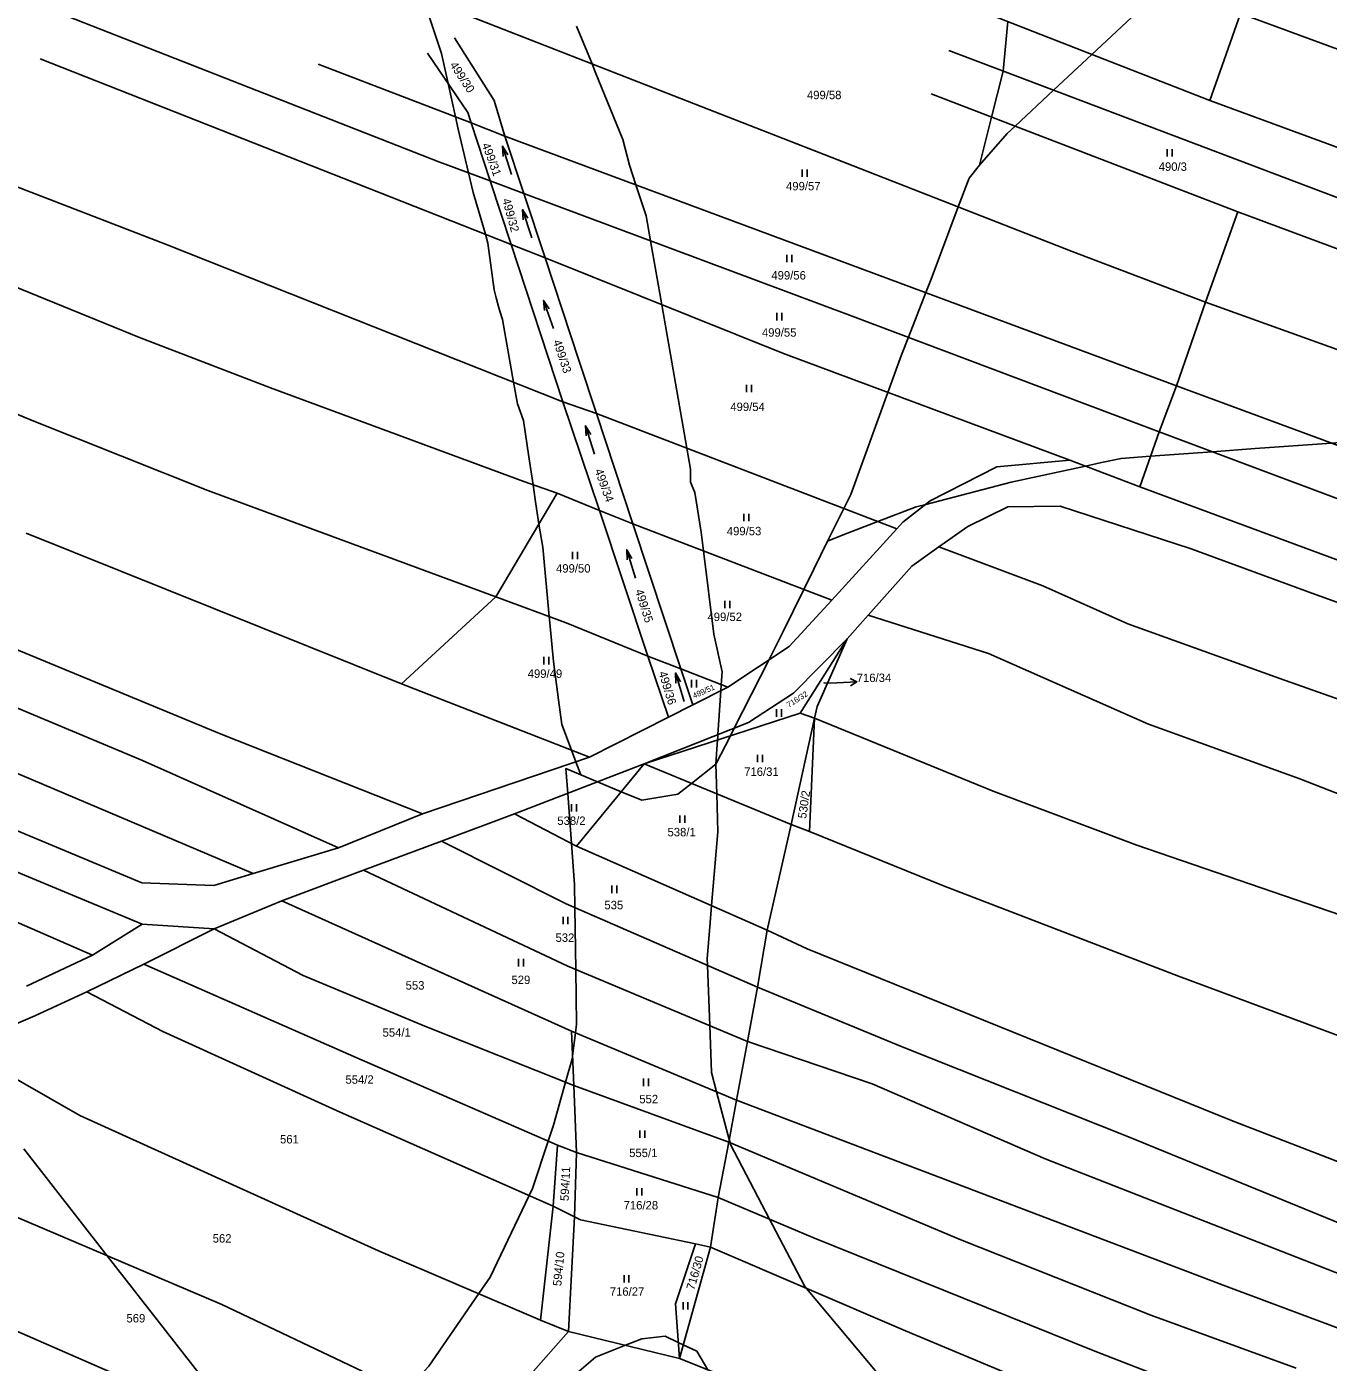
# Model space of a CAD drawing. Extents: x -749173 to -746119, y -1132678 to -1130338.
# Drawn here: x -748430.5 to -748168.2, y -1130971 to -1130701.9 of the extents above; entities that cross this region are included whole.
import ezdxf

# ---------------------------------------------------------------- set-up
doc = ezdxf.new("R2010")
doc.units = 0
for name, color, linetype in [('Vrstva 1', 7, 'Continuous'), ('Vrstva 16', 7, 'Continuous'), ('Vrstva 18', 7, 'Continuous'), ('Vrstva 25', 7, 'Continuous'), ('Vrstva 52', 7, 'Continuous'), ('Vrstva 6', 7, 'Continuous')]:
    doc.layers.add(name, color=color, linetype=linetype)

msp = doc.modelspace()

# ---------------------------------------------------------------- linework, layer by layer
at = {"layer": 'Vrstva 1'}
for points in [[(-748336.28, -1130716.76), (-748344.32, -1130704.11)], [(-748349.74, -1130707.22), (-748341.63, -1130719.17)], [(-748334.14, -1130723.95), (-748336.28, -1130716.76)], [(-748341.63, -1130719.17), (-748340.95, -1130721.23)], [(-748340.95, -1130721.23), (-748337.1, -1130732.95)], [(-748330.34, -1130735.47), (-748334.14, -1130723.95)], [(-748337.1, -1130732.95), (-748332.9, -1130745.74)], [(-748326.07, -1130748.44), (-748330.34, -1130735.47)], [(-748332.9, -1130745.74), (-748322.49, -1130777.44)], [(-748319.21, -1130769.27), (-748326.07, -1130748.44)], [(-748315.72, -1130779.81), (-748319.21, -1130769.27)], [(-748322.49, -1130777.44), (-748315.11, -1130799.35)], [(-748308.36, -1130802.04), (-748315.72, -1130779.81)], [(-748235.03, -1130790.57), (-748248.44, -1130797.43)], [(-748220.29, -1130789.23), (-748235.03, -1130790.57)], [(-748206.22, -1130794.61), (-748220.29, -1130789.23)], [(-748116.18, -1130827.89), (-748206.22, -1130794.61)], [(-748248.44, -1130797.43), (-748253.94, -1130801.72)], [(-748240.86, -1130802.57), (-748232.82, -1130798.59)], [(-748232.82, -1130798.59), (-748222.25, -1130798.5)], [(-748222.25, -1130798.5), (-748195.87, -1130807.09)], [(-748315.11, -1130799.35), (-748305.32, -1130828.72)], [(-748253.94, -1130801.72), (-748255.16, -1130803.06)], [(-748298.68, -1130831.28), (-748308.36, -1130802.04)], [(-748255.16, -1130803.06), (-748268.27, -1130817.4)], [(-748246.71, -1130806.7), (-748240.86, -1130802.57)], [(-748252.18, -1130810.57), (-748246.71, -1130806.7)], [(-748195.87, -1130807.09), (-748171.55, -1130816.01)], [(-748260.98, -1130820.46), (-748252.18, -1130810.57)], [(-748268.27, -1130817.4), (-748276.84, -1130826.78)], [(-748171.55, -1130816.01), (-748091.95, -1130844.69)], [(-748265.19, -1130825.19), (-748260.98, -1130820.46)], [(-748265.19, -1130825.19), (-748276.01, -1130836.18)], [(-748271.25, -1130838.88), (-748265.19, -1130825.19)], [(-748305.32, -1130828.72), (-748301.18, -1130841.02)], [(-748276.84, -1130826.78), (-748289.25, -1130834.98)], [(-748296.28, -1130838.54), (-748298.68, -1130831.28)], [(-748407.29, -1130874.39), (-748504.41, -1130833.78)], [(-748289.25, -1130834.98), (-748296.28, -1130838.54)], [(-748285.08, -1130842.06), (-748276.01, -1130836.18)], [(-748296.28, -1130838.54), (-748301.18, -1130841.02)], [(-748271.76, -1130841.22), (-748271.25, -1130838.88)], [(-748301.18, -1130841.02), (-748317.07, -1130849.07)], [(-748306.12, -1130850.42), (-748285.08, -1130842.06)], [(-748276.46, -1130862.6), (-748271.76, -1130841.22)], [(-748317.07, -1130849.07), (-748350.77, -1130860.5)], [(-748332.19, -1130860.47), (-748306.12, -1130850.42)], [(-748464.71, -1130858.77), (-748407.23, -1130882.69)], [(-748350.77, -1130860.5), (-748367.71, -1130867.32)], [(-748346.93, -1130865.99), (-748332.19, -1130860.47)], [(-748281.3, -1130883.89), (-748276.46, -1130862.6)], [(-748362.61, -1130871.86), (-748346.93, -1130865.99)], [(-748367.71, -1130867.32), (-748384.89, -1130872.51)], [(-748379.12, -1130878.04), (-748362.61, -1130871.86)], [(-748392.79, -1130874.89), (-748407.29, -1130874.39)], [(-748384.89, -1130872.51), (-748392.79, -1130874.89)], [(-748392.75, -1130883.62), (-748379.12, -1130878.04)], [(-748379.12, -1130878.04), (-748320.72, -1130904.27)], [(-748417.27, -1130888.93), (-748407.23, -1130882.69)], [(-748407.23, -1130882.69), (-748392.75, -1130883.62)], [(-748406.9, -1130890.75), (-748392.75, -1130883.62)], [(-748283.22, -1130895.4), (-748281.3, -1130883.89)], [(-748430.56, -1130895.23), (-748417.27, -1130888.93)], [(-748418.37, -1130896.38), (-748406.9, -1130890.75)], [(-748285.26, -1130906.35), (-748283.22, -1130895.4)], [(-748428.88, -1130901.17), (-748418.37, -1130896.38)], [(-748443.77, -1130907.57), (-748428.88, -1130901.17)], [(-748320.72, -1130904.27), (-748320.27, -1130915.24)], [(-748287.49, -1130918.18), (-748285.26, -1130906.35)], [(-748320.27, -1130915.24), (-748319.71, -1130928.71)], [(-748289.04, -1130926.63), (-748287.49, -1130918.18)], [(-748291.2, -1130937.79), (-748289.04, -1130926.63)], [(-748319.71, -1130928.71), (-748320.15, -1130941.67)], [(-748292.72, -1130947.82), (-748291.2, -1130937.79)], [(-748320.15, -1130941.67), (-748321.33, -1130964.79)], [(-748298.99, -1130970.22), (-748292.72, -1130947.82)], [(-748321.33, -1130964.79), (-748338.46, -1130984.21)], [(-748225.2, -1130999.57), (-748298.99, -1130970.22)]]:
    msp.add_lwpolyline(points, dxfattribs=at)
at = {"layer": 'Vrstva 16'}
msp.add_line((-748264.6, -1130833.18), (-748263.26, -1130833.87), dxfattribs=at)
for points in [[(-748269.9, -1130834.17), (-748267.26, -1130834.05)], [(-748267.26, -1130834.05), (-748263.26, -1130833.87), (-748264.53, -1130834.68)]]:
    msp.add_lwpolyline(points, dxfattribs=at)
at = {"layer": 'Vrstva 25'}
for p, q in [((-748332.82, -1130731.65), (-748334.64, -1130725.93)), ((-748200.71, -1130726.51), (-748200.71, -1130728.01)), ((-748199.71, -1130728.01), (-748199.71, -1130726.51)), ((-748274.26, -1130730.64), (-748274.26, -1130732.14)), ((-748273.26, -1130732.14), (-748273.26, -1130730.64)), ((-748328.69, -1130744.39), (-748330.61, -1130738.71)), ((-748277.32, -1130747.83), (-748277.32, -1130749.33)), ((-748276.32, -1130749.33), (-748276.32, -1130747.83)), ((-748324.36, -1130762.67), (-748326.36, -1130757.01)), ((-748279.33, -1130759.54), (-748279.33, -1130761.04)), ((-748278.33, -1130761.04), (-748278.33, -1130759.54)), ((-748285.45, -1130774.02), (-748285.45, -1130775.52)), ((-748284.45, -1130775.52), (-748284.45, -1130774.02)), ((-748316.09, -1130787.99), (-748317.93, -1130782.29)), ((-748286, -1130800), (-748286, -1130801.5)), ((-748285, -1130801.5), (-748285, -1130800)), ((-748307.84, -1130812.99), (-748309.6, -1130807.25)), ((-748320.55, -1130807.67), (-748320.55, -1130809.17)), ((-748319.55, -1130809.17), (-748319.55, -1130807.67)), ((-748289.8, -1130817.54), (-748289.8, -1130819.04)), ((-748288.8, -1130819.04), (-748288.8, -1130817.54)), ((-748326.33, -1130828.87), (-748326.33, -1130830.37)), ((-748325.33, -1130830.37), (-748325.33, -1130828.87)), ((-748298.04, -1130837.83), (-748299.8, -1130832.09)), ((-748296.53, -1130833.5), (-748296.53, -1130835)), ((-748295.53, -1130835), (-748295.53, -1130833.5)), ((-748279.42, -1130839.41), (-748279.42, -1130840.91)), ((-748278.42, -1130840.91), (-748278.42, -1130839.41)), ((-748283.27, -1130848.58), (-748283.27, -1130850.08)), ((-748282.27, -1130850.08), (-748282.27, -1130848.58)), ((-748320.75, -1130858.52), (-748320.75, -1130860.02)), ((-748319.75, -1130860.02), (-748319.75, -1130858.52)), ((-748298.91, -1130860.81), (-748298.91, -1130862.31)), ((-748297.91, -1130862.31), (-748297.91, -1130860.81)), ((-748312.61, -1130874.94), (-748312.61, -1130876.44)), ((-748311.61, -1130876.44), (-748311.61, -1130874.94)), ((-748322.44, -1130881.21), (-748322.44, -1130882.71)), ((-748321.44, -1130882.71), (-748321.44, -1130881.21)), ((-748331.4, -1130889.71), (-748331.4, -1130891.21)), ((-748330.4, -1130891.21), (-748330.4, -1130889.71)), ((-748306.24, -1130913.83), (-748306.24, -1130915.33)), ((-748305.24, -1130915.33), (-748305.24, -1130913.83)), ((-748306.95, -1130924.29), (-748306.95, -1130925.79)), ((-748305.95, -1130925.79), (-748305.95, -1130924.29)), ((-748307.56, -1130935.88), (-748307.56, -1130937.38)), ((-748306.56, -1130937.38), (-748306.56, -1130935.88)), ((-748310.15, -1130953.45), (-748310.15, -1130954.95)), ((-748309.15, -1130954.95), (-748309.15, -1130953.45)), ((-748298.26, -1130958.89), (-748298.26, -1130960.39)), ((-748297.26, -1130960.39), (-748297.26, -1130958.89))]:
    msp.add_line(p, q, dxfattribs=at)
for points in [[(-748334.51, -1130727.99), (-748334.64, -1130725.93), (-748333.56, -1130727.69)], [(-748330.44, -1130740.76), (-748330.61, -1130738.71), (-748329.5, -1130740.44)], [(-748326.16, -1130759.06), (-748326.36, -1130757.01), (-748325.22, -1130758.73)], [(-748317.79, -1130784.34), (-748317.93, -1130782.29), (-748316.84, -1130784.03)], [(-748309.49, -1130809.31), (-748309.6, -1130807.25), (-748308.54, -1130809.02)], [(-748299.69, -1130834.15), (-748299.8, -1130832.09), (-748298.74, -1130833.86)]]:
    msp.add_lwpolyline(points, dxfattribs=at)
at = {"layer": 'Vrstva 52'}
for points in [[(-748349.45, -1130699.63), (-748346.94, -1130707.25), (-748345.59, -1130713.34), (-748344.11, -1130720.02), (-748343.56, -1130722.5), (-748341.49, -1130731.31), (-748340.56, -1130735.25), (-748338.09, -1130743.69), (-748337.56, -1130745.5), (-748336.31, -1130754.87), (-748335.89, -1130756.5), (-748335.44, -1130758.25), (-748335.16, -1130759.16), (-748334.62, -1130760.87)], [(-748291.62, -1130850.5), (-748291.42, -1130847.43), (-748291.3, -1130845.61), (-748291.26, -1130845.05), (-748291.22, -1130844.5), (-748290.63, -1130835.68), (-748290.55, -1130834.47), (-748290.37, -1130831.87), (-748292.06, -1130824.25), (-748294.16, -1130807.48), (-748294.62, -1130803.75), (-748295.87, -1130795.75), (-748296.75, -1130793.62), (-748296.75, -1130791), (-748297.48, -1130786.81), (-748302.55, -1130757.88), (-748304.81, -1130745), (-748305.69, -1130740), (-748307.75, -1130733.75), (-748309.06, -1130729.75), (-748310.37, -1130724.62), (-748315.94, -1130710.96), (-748316.59, -1130709.36), (-748319.69, -1130701.75)], [(-748238.5, -1130729.75), (-748232.94, -1130723.37), (-748231.36, -1130721.9), (-748223.59, -1130714.66), (-748215.86, -1130707.45), (-748207.87, -1130700)], [(-748238.5, -1130729.75), (-748236.07, -1130720.1), (-748233.81, -1130711.12), (-748233.78, -1130710.8), (-748232.81, -1130700.81)], [(-748269.12, -1130805.5), (-748265.85, -1130798.95), (-748264.44, -1130796.12), (-748256.99, -1130775.56), (-748254.25, -1130768), (-748252.85, -1130764.44), (-748249.31, -1130755.45), (-748248.25, -1130752.75), (-748242.79, -1130738.17), (-748240.62, -1130732.37), (-748238.5, -1130729.75)], [(-748334.62, -1130760.87), (-748332.39, -1130773.51), (-748331.62, -1130777.87), (-748330.37, -1130781.25), (-748329.3, -1130788.56), (-748328.48, -1130794.15), (-748328.04, -1130797.13), (-748327.37, -1130801.62), (-748327.3, -1130802.08), (-748326.5, -1130806.75), (-748325.21, -1130820.72), (-748325.15, -1130821.35), (-748324.37, -1130829.75), (-748323.35, -1130837.51), (-748322.69, -1130842.5), (-748321.95, -1130844.45), (-748320.75, -1130847.64), (-748319.86, -1130850.01), (-748318.87, -1130852.62)], [(-748092.85, -1130784.45), (-748119.44, -1130784.28), (-748123.54, -1130784.26), (-748124.94, -1130784.25), (-748152.19, -1130784.62), (-748162.19, -1130785.36), (-748167.62, -1130785.76), (-748182.96, -1130786.89), (-748191.61, -1130787.52), (-748204.04, -1130788.43), (-748210, -1130788.87), (-748213.91, -1130789.71), (-748217.19, -1130790.42), (-748232.12, -1130793.62), (-748249.33, -1130798.12), (-748251.25, -1130798.62), (-748258.98, -1130801.59), (-748265.99, -1130804.29), (-748269.12, -1130805.5)], [(-748291.62, -1130850.5), (-748288.72, -1130844.78), (-748287.92, -1130843.19), (-748280.99, -1130829.52), (-748278.06, -1130823.75), (-748273.9, -1130815.24), (-748271.9, -1130811.16), (-748269.12, -1130805.5)], [(-748318.87, -1130852.62), (-748321.87, -1130851.37), (-748321.5, -1130856.35), (-748320.75, -1130866.43), (-748320.12, -1130874.75), (-748320.05, -1130879.41), (-748319.86, -1130891.82), (-748319.69, -1130902.87), (-748319.91, -1130904.61), (-748320.52, -1130909.26), (-748320.56, -1130909.62), (-748321.95, -1130914.57), (-748324.37, -1130923.25), (-748325.44, -1130926.45), (-748328.62, -1130936), (-748329.29, -1130937.4), (-748337.12, -1130953.87), (-748339.41, -1130957.17), (-748349.5, -1130971.75), (-748354.17, -1130976.86), (-748368.65, -1130994.51), (-748369.87, -1130996), (-748372, -1130998.12)], [(-748291.62, -1130850.5), (-748296.56, -1130854.35), (-748299.31, -1130856.5), (-748306.56, -1130857.75), (-748310.71, -1130856.02), (-748315.49, -1130854.03), (-748318.87, -1130852.62)], [(-748291.46, -1130856.44), (-748291.62, -1130850.5)], [(-748256.75, -1130976), (-748273.41, -1130956.1), (-748273.81, -1130955.62), (-748280.24, -1130943.32), (-748280.85, -1130942.14), (-748288.69, -1130927.12), (-748288.79, -1130926.73), (-748288.95, -1130926.13), (-748291.48, -1130916.51), (-748292.5, -1130912.62), (-748292.86, -1130903.16), (-748293.32, -1130891.02), (-748293.37, -1130889.62), (-748292.85, -1130883.27), (-748292.49, -1130878.96), (-748291.25, -1130864.12), (-748291.46, -1130856.44)], [(-748431.12, -1130928), (-748414.3, -1130949.53), (-748388.62, -1130982.37), (-748385.85, -1130985), (-748383.38, -1130987.35), (-748375.86, -1130994.47), (-748372, -1130998.12)], [(-748324.37, -1130977.25), (-748315.87, -1130970), (-748309.86, -1130967.58), (-748306.56, -1130966.25), (-748301.87, -1130965.75), (-748299.22, -1130967), (-748298.22, -1130967.47), (-748295.5, -1130968.75), (-748293.28, -1130972.49)]]:
    msp.add_lwpolyline(points, dxfattribs=at)
at = {"layer": 'Vrstva 6'}
for points in [[(-748192.08, -1130716.76), (-748280.18, -1130682.27)], [(-748347.47, -1130729.08), (-748459.12, -1130685.32)], [(-748267.04, -1130728.69), (-748344.18, -1130698.6)], [(-748185.93, -1130699.2), (-748192.08, -1130716.76)], [(-748116.35, -1130724.81), (-748185.93, -1130699.2)], [(-748244.7, -1130706.67), (-748172.71, -1130733.91)], [(-748427.81, -1130708.36), (-748359.6, -1130735.19)], [(-748371.81, -1130709.41), (-748340.95, -1130721.23)], [(-748248.26, -1130715.42), (-748186.46, -1130739.14)], [(-748192.08, -1130716.76), (-748141.67, -1130735.26)], [(-748402.55, -1130745.71), (-748463.67, -1130722.09)], [(-748340.95, -1130721.23), (-748334.14, -1130723.95)], [(-748334.14, -1130723.95), (-748264.42, -1130749.83)], [(-748337.1, -1130732.95), (-748347.47, -1130729.08)], [(-748219.82, -1130747.15), (-748267.04, -1130728.69)], [(-748330.34, -1130735.47), (-748337.1, -1130732.95)], [(-748172.71, -1130733.91), (-748157.04, -1130739.82)], [(-748359.6, -1130735.19), (-748332.9, -1130745.74)], [(-748264.68, -1130759.98), (-748330.34, -1130735.47)], [(-748529.63, -1130739.69), (-748429.06, -1130781.38)], [(-748424.93, -1130757.48), (-748468.11, -1130739.92)], [(-748186.46, -1130739.14), (-748192.95, -1130757.36)], [(-748186.46, -1130739.14), (-748156.81, -1130750.21)], [(-748322.49, -1130777.44), (-748402.55, -1130745.71)], [(-748332.9, -1130745.74), (-748326.07, -1130748.44)], [(-748192.95, -1130757.36), (-748219.82, -1130747.15)], [(-748326.07, -1130748.44), (-748278.03, -1130767.72)], [(-748264.42, -1130749.83), (-748198.84, -1130774.24)], [(-748407.79, -1130764.49), (-748424.93, -1130757.48)], [(-748192.95, -1130757.36), (-748198.84, -1130774.24)], [(-748149.26, -1130773.11), (-748192.95, -1130757.36)], [(-748202.3, -1130783.51), (-748264.68, -1130759.98)], [(-748381.4, -1130774.63), (-748407.79, -1130764.49)], [(-748278.03, -1130767.72), (-748220.29, -1130789.23)], [(-748330.32, -1130793.51), (-748381.4, -1130774.63)], [(-748198.84, -1130774.24), (-748202.3, -1130783.51)], [(-748124.83, -1130801.55), (-748198.84, -1130774.24)], [(-748315.72, -1130779.81), (-748322.49, -1130777.44)], [(-748255.16, -1130803.06), (-748315.72, -1130779.81)], [(-748429.06, -1130781.38), (-748394.01, -1130795.35)], [(-748202.3, -1130783.51), (-748206.22, -1130794.61)], [(-748202.3, -1130783.51), (-748146.21, -1130804.55)], [(-748323.6, -1130795.85), (-748330.32, -1130793.51)], [(-748394.01, -1130795.35), (-748336, -1130816.73)], [(-748336, -1130816.73), (-748323.6, -1130795.85)], [(-748323.6, -1130795.85), (-748315.11, -1130799.35)], [(-748315.11, -1130799.35), (-748308.36, -1130802.04)], [(-748354.99, -1130834.29), (-748430.59, -1130803.91)], [(-748308.36, -1130802.04), (-748268.27, -1130817.4)], [(-748246.71, -1130806.7), (-748225.74, -1130814.53)], [(-748225.74, -1130814.53), (-748208.63, -1130822.17)], [(-748354.99, -1130834.29), (-748336, -1130816.73)], [(-748321.79, -1130821.98), (-748336, -1130816.73)], [(-748236.71, -1130828.16), (-748260.98, -1130820.46)], [(-748429.14, -1130840.54), (-748472.42, -1130822.39)], [(-748391.34, -1130844.41), (-748448.56, -1130820.81)], [(-748305.32, -1130828.72), (-748321.79, -1130821.98)], [(-748208.63, -1130822.17), (-748178, -1130833.24)], [(-748274.62, -1130840.2), (-748265.19, -1130825.19)], [(-748305.32, -1130828.72), (-748298.68, -1130831.28)], [(-748204.44, -1130842.38), (-748236.71, -1130828.16)], [(-748289.25, -1130834.98), (-748298.68, -1130831.28)], [(-748178, -1130833.24), (-748153.66, -1130841.78)], [(-748317.07, -1130849.07), (-748354.99, -1130834.29)], [(-748407.16, -1130849.74), (-748429.14, -1130840.54)], [(-748306.12, -1130850.42), (-748274.62, -1130840.2)], [(-748274.62, -1130840.2), (-748271.76, -1130841.22)], [(-748271.76, -1130841.22), (-748272.8, -1130864.07)], [(-748271.76, -1130841.22), (-748235.77, -1130855.93)], [(-748350.77, -1130860.5), (-748391.34, -1130844.41)], [(-748173.97, -1130853.4), (-748204.44, -1130842.38)], [(-748440.81, -1130848.76), (-748384.89, -1130872.51)], [(-748367.71, -1130867.32), (-748407.16, -1130849.74)], [(-748319.69, -1130866.98), (-748306.12, -1130850.42)], [(-748276.46, -1130862.6), (-748306.12, -1130850.42)], [(-748129.42, -1130870.81), (-748173.97, -1130853.4)], [(-748235.77, -1130855.93), (-748206.84, -1130866.81)], [(-748417.27, -1130888.93), (-748482.75, -1130860.42)], [(-748332.19, -1130860.47), (-748319.69, -1130866.98)], [(-748272.8, -1130864.07), (-748276.46, -1130862.6)], [(-748321.83, -1130878.64), (-748346.93, -1130865.99)], [(-748245.75, -1130874.96), (-748272.8, -1130864.07)], [(-748319.69, -1130866.98), (-748281.3, -1130883.89)], [(-748206.84, -1130866.81), (-748165.74, -1130880.87)], [(-748321.46, -1130891.15), (-748362.61, -1130871.86)], [(-748198.42, -1130893.2), (-748245.75, -1130874.96)], [(-748283.22, -1130895.4), (-748321.83, -1130878.64)], [(-748392.75, -1130883.62), (-748374.81, -1130893.06)], [(-748281.3, -1130883.89), (-748273.25, -1130887.68)], [(-748273.25, -1130887.68), (-748187.39, -1130922.39)], [(-748406.9, -1130890.75), (-748364, -1130909.67)], [(-748374.81, -1130893.06), (-748350.31, -1130903.3)], [(-748285.26, -1130906.35), (-748321.46, -1130891.15)], [(-748130.17, -1130918.61), (-748198.42, -1130893.2)], [(-748283.22, -1130895.4), (-748254.13, -1130907.42)], [(-748418.37, -1130896.38), (-748403.05, -1130904.37)], [(-748350.31, -1130903.3), (-748320.27, -1130915.24)], [(-748403.05, -1130904.37), (-748367.33, -1130920.63)], [(-748320.72, -1130904.27), (-748287.49, -1130918.18)], [(-748260.16, -1130914.87), (-748285.26, -1130906.35)], [(-748419.77, -1130921.28), (-748443.77, -1130907.57)], [(-748254.13, -1130907.42), (-748208.52, -1130925.59)], [(-748364, -1130909.67), (-748323.55, -1130927.27)], [(-748225.28, -1130930), (-748260.16, -1130914.87)], [(-748289.04, -1130926.63), (-748320.27, -1130915.24)], [(-748287.49, -1130918.18), (-748188.9, -1130955.67)], [(-748359.61, -1130948.54), (-748419.77, -1130921.28)], [(-748367.33, -1130920.63), (-748324.42, -1130939.55)], [(-748187.39, -1130922.39), (-748125.51, -1130946.33)], [(-748208.52, -1130925.59), (-748165.81, -1130943.03)], [(-748323.55, -1130927.27), (-748324.42, -1130939.55)], [(-748319.71, -1130928.71), (-748323.55, -1130927.27)], [(-748289.04, -1130926.63), (-748242.28, -1130946.35)], [(-748291.2, -1130937.79), (-748319.71, -1130928.71)], [(-748156.11, -1130957.09), (-748225.28, -1130930)], [(-748272.09, -1130945.83), (-748291.2, -1130937.79)], [(-748437.34, -1130939.73), (-748391.2, -1130959.35)], [(-748324.42, -1130939.55), (-748326.95, -1130962.5)], [(-748320.15, -1130941.67), (-748324.42, -1130939.55)], [(-748318.91, -1130942.31), (-748320.15, -1130941.67)], [(-748295.77, -1130947.1), (-748318.91, -1130942.31)], [(-748299.79, -1130959.24), (-748295.77, -1130947.1)], [(-748295.77, -1130947.1), (-748292.72, -1130947.82)], [(-748215.31, -1130968.76), (-748272.09, -1130945.83)], [(-748242.28, -1130946.35), (-748203.98, -1130961.53)], [(-748326.95, -1130962.5), (-748359.61, -1130948.54)], [(-748292.72, -1130947.82), (-748253.46, -1130964.66)], [(-748188.9, -1130955.67), (-748145.76, -1130971.78)], [(-748391.2, -1130959.35), (-748362.89, -1130972.76)], [(-748298.99, -1130970.22), (-748299.79, -1130959.24)], [(-748326.95, -1130962.5), (-748321.33, -1130964.79)], [(-748203.98, -1130961.53), (-748174.74, -1130972.17)], [(-748406.22, -1130976.23), (-748433.55, -1130964.26)], [(-748321.33, -1130964.79), (-748298.99, -1130970.22)], [(-748253.46, -1130964.66), (-748231.13, -1130974.02)], [(-748170.66, -1130986.1), (-748215.31, -1130968.76)]]:
    msp.add_lwpolyline(points, dxfattribs=at)

# ---------------------------------------------------------------- texts
at = {"layer": 'Vrstva 16'}
msp.add_text('716/34', height=1.7, dxfattribs=at).set_placement((-748263.26, -1130833.92))
at = {"layer": 'Vrstva 18'}
for s, height, rotation, p in [('499/30', 1.7, 303.3121, (-748345.35, -1130709.57)), ('499/31', 1.7, 290.3441, (-748338.82, -1130725.63)), ('499/32', 1.7, 285.3199, (-748334.71, -1130736.7)), ('499/33', 1.7, 288.3415, (-748324.48, -1130765.26)), ('499/34', 1.7, 289.795, (-748316.09, -1130791.29)), ('499/35', 1.7, 287.4549, (-748307.93, -1130815.51)), ('499/36', 1.7, 286.9051, (-748303.2, -1130832.03)), ('716/34', 0.1, 66.0375, (-748269.9, -1130834.17)), ('499/51', 1.14, 24.1839, (-748296, -1130837.27)), ('716/32', 1.14, 32.2547, (-748276.92, -1130839.12)), ('530/2', 1.7, 81.6037, (-748273.46, -1130861.53)), ('594/11', 1.7, 87.2919, (-748321.31, -1130938.54)), ('594/10', 1.7, 84.5268, (-748322.8, -1130955.72)), ('716/30', 1.7, 73.9358, (-748296, -1130956.56))]:
    msp.add_text(s, height=height, rotation=rotation, dxfattribs=at).set_placement(p)
for s, p in [('499/58', (-748273.29, -1130716.47)), ('490/3', (-748202.41, -1130730.91)), ('499/57', (-748277.5, -1130734.84)), ('499/56', (-748280.46, -1130752.81)), ('499/55', (-748282.36, -1130764.33)), ('499/54', (-748288.73, -1130779.31)), ('499/53', (-748289.43, -1130804.35)), ('499/50', (-748323.85, -1130811.87)), ('499/52', (-748293.33, -1130821.63)), ('499/49', (-748329.56, -1130833.07)), ('716/31', (-748285.93, -1130852.84)), ('538/2', (-748323.59, -1130862.72)), ('538/1', (-748301.38, -1130865.01)), ('535', (-748314.1, -1130879.71)), ('532', (-748323.95, -1130886.28)), ('529', (-748332.83, -1130894.78)), ('553', (-748354.15, -1130895.9)), ('554/1', (-748358.8, -1130905.39)), ('554/2', (-748366.28, -1130914.87)), ('552', (-748307.07, -1130918.81)), ('561', (-748379.46, -1130926.9)), ('555/1', (-748309.11, -1130929.65)), ('716/28', (-748310.23, -1130940.2)), ('562', (-748393.03, -1130946.88)), ('716/27', (-748313.01, -1130957.59)), ('569', (-748410.41, -1130962.97))]:
    msp.add_text(s, height=1.7, dxfattribs=at).set_placement(p)

doc.saveas('drawing.dxf')
